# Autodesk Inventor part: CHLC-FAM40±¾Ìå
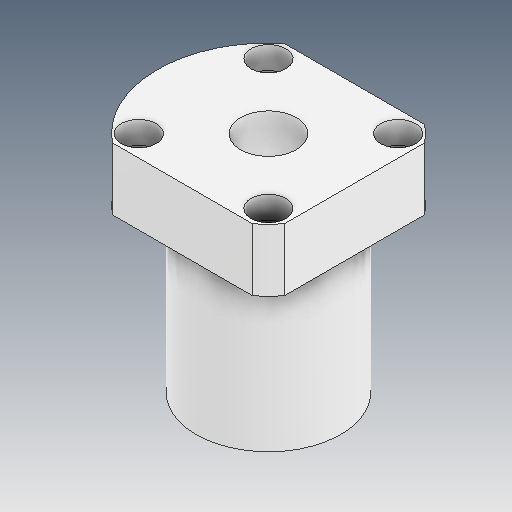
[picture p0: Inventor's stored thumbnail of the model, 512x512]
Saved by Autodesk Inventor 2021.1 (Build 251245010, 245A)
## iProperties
Created: 2021-05
Part Number: CHLC-FAM40±¾Ìå
Material: Ogólny
Document SubType Name: Modeling
Designer: user
Density: 1 g/cm^3
Appearance: Domyślna
Author: user
Revision Number: ÈÎºÎ
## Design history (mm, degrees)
feature "ÊäÈë2"
feature "ÇÐ³ý-À­Éì1" [ÊäÈë]
node "Bryła1"
node "Bryła2"
